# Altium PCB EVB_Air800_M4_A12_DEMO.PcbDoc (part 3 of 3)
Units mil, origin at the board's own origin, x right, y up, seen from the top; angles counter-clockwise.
Board outline 2106 x 2583.39 mil, 2 copper layers (Top, Bottom), stack 12.7 mil thick; 125 components, 94 nets, 414 pads, 454 vias.
Unrouted connection lines stored in the file: 290.
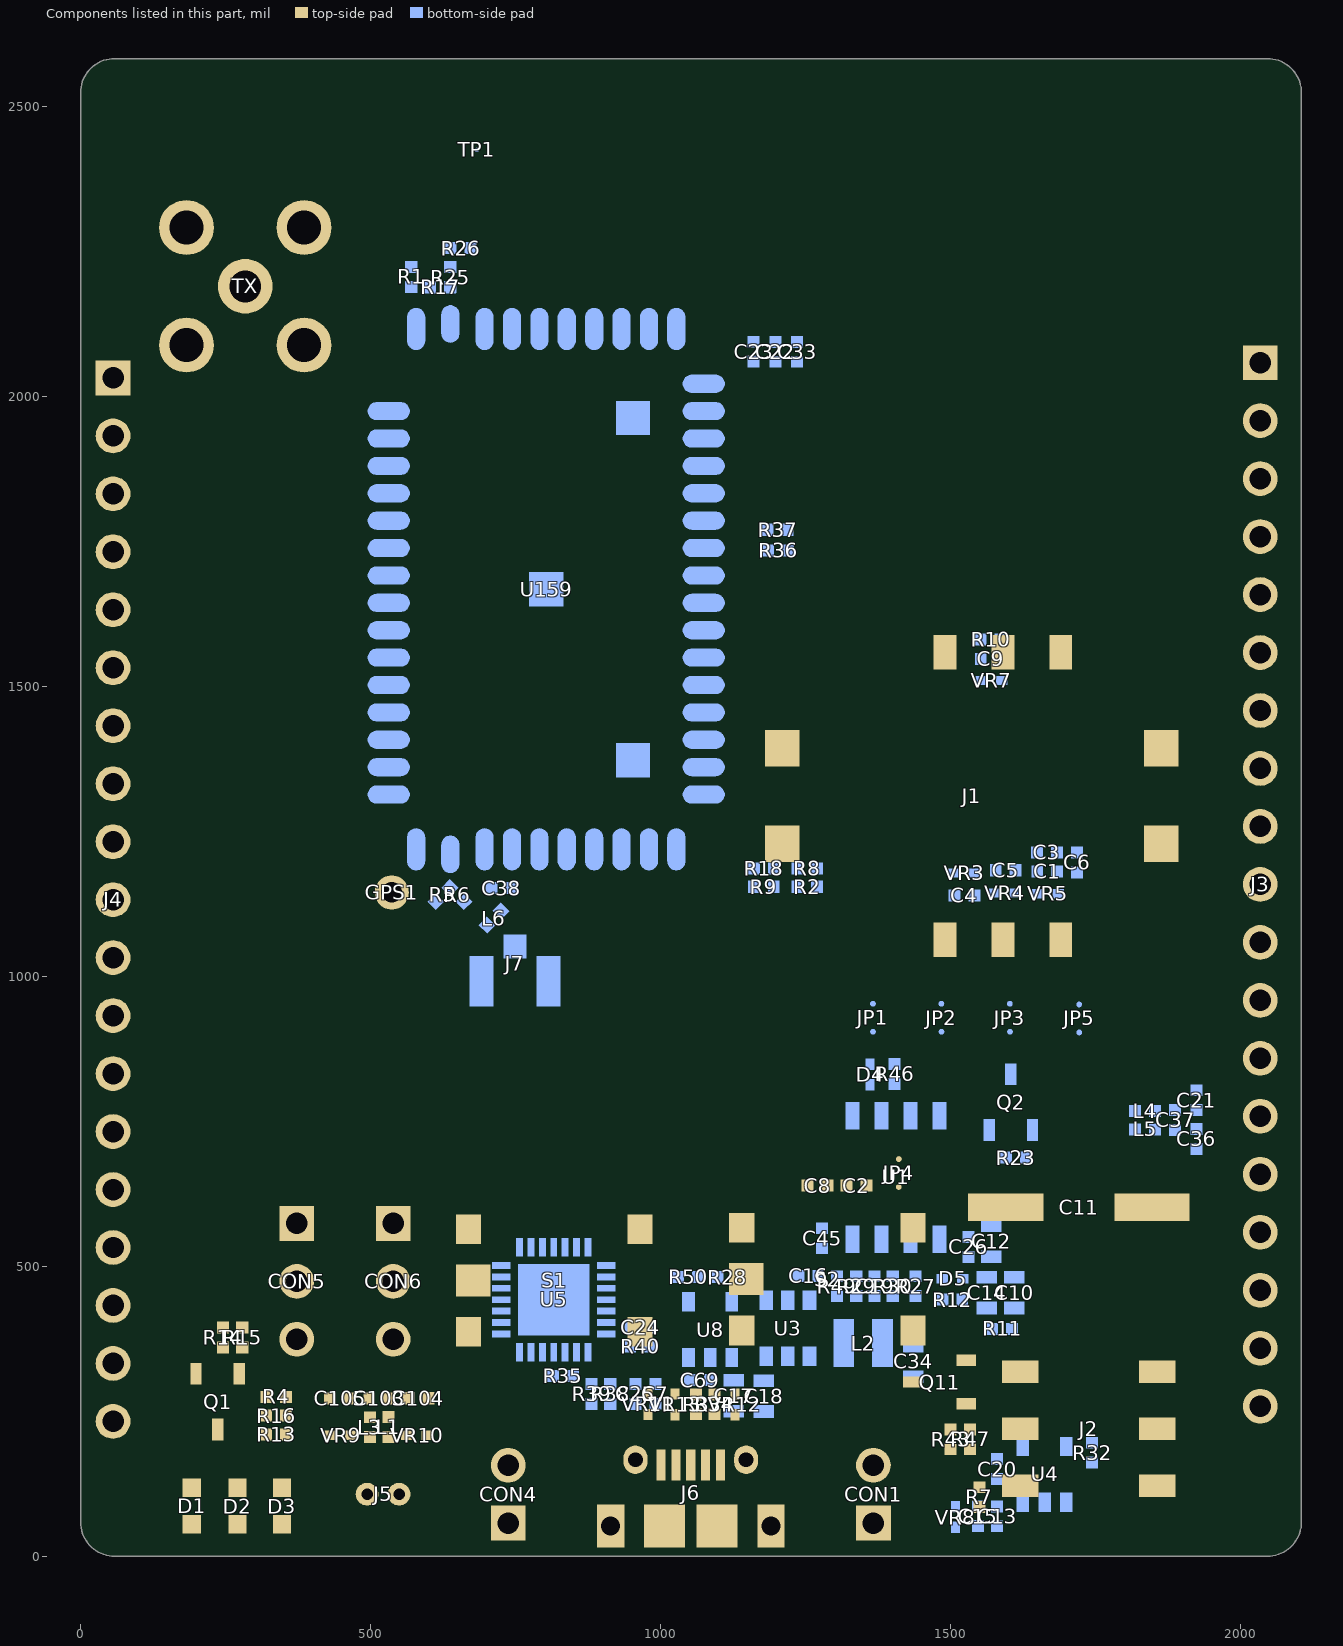
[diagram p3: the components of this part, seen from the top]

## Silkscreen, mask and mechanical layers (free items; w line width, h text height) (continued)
Silkscreen Bottom:
  text "VBAT" at 1980.05,2041.84 h47.24
  text "VRTC" at 236.94,1991.39 h47.24
  text "VBAT" at 1980.05,1941.84 h47.24
  text "GND" at 213.12,1916.64 h47.24
  text "GND" at 1980.05,1841.84 h47.24
  text "LCD_CS/GPIO15" at 450.07,1816.64 h47.24
  text "PWRKEY" at 1980.05,1741.84 h47.24
  text "LCD_CLK/GPIO16" at 473.36,1716.64 h47.24
  text "GPIO28" at 1980.05,1641.84 h47.24
  text "LCD_DATA/GPIO17" at 503.86,1616.64 h47.24
  text "UART2_CTS/GPIO7" at 1980.05,1541.84 h47.24
  text "LCD_DC/GPIO18" at 452.21,1516.64 h47.24
  text "UART2_RTS/GPIO6" at 1980.05,1441.84 h47.24
  text "VDDIO" at 255.51,1416.64 h47.24
  text "UART1_CTS/GPIO3" at 1980.05,1341.84 h47.24
  text "LCD_RST/GPIO14" at 475.54,1316.64 h47.24
  text "UART1_RTS/GPIO2" at 1980.05,1241.84 h47.24
  text "RESET" at 260.41,1216.64 h47.24
  text "ADC0" at 1980.05,1141.84 h47.24
  text "UART1_DTR/GPIO29" at 531.83,1116.64 h47.24
  text "ADC1" at 1980.05,1041.84 h47.24
  text "UART1_DCD/GPIO31" at 530.6,1016.64 h47.24
  text "JP1" at 1402.92,994.51 h47.24
  text "JP2" at 1517.45,994.51 h47.24
  text "JP3" at 1634.71,994.51 h47.24
  text "JP5" at 1756.94,994.51 h47.24
  text "GPS_TXD" at 1980.05,941.84 h47.24
  text "UART1_RI/GPIO30" at 487.12,916.64 h47.24
  text "GPIO13" at 1980.05,841.84 h47.24
  text "LDO_VIB" at 296.9,816.64 h47.24
  text "SPI1_DI/GPIO12" at 441.41,716.25 h47.24
  text "SPK+" at 1945.6,711.93 h47.24 r270
  text "SPK-" at 1980.05,641.84 h47.24
  text "GPIO11" at 266.39,615.85 h47.24
  text "GND" at 1980.05,541.84 h47.24
  text "GPIO10" at 268.23,515.46 h47.24
  text "UART1_TXD/GPIO1" at 1980.05,441.84 h47.24
  text "GPIO8" at 244.85,415.07 h47.24
  text "UART1_RXD/GPIO0" at 1980.05,341.84 h47.24
  text "GPIO9" at 244.85,314.67 h47.24
  text "VBUS" at 1980.05,241.84 h47.24
  text "GPIO34" at 268.18,216.25 h47.24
